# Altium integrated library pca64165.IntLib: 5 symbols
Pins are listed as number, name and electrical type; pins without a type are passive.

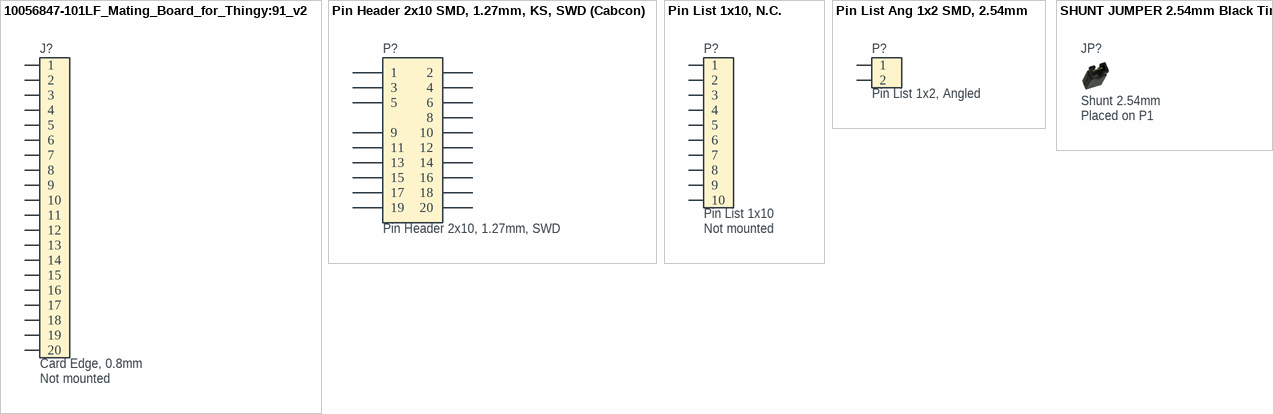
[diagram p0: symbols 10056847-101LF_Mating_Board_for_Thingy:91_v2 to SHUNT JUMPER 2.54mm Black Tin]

## 10056847-101LF_Mating_Board_for_Thingy:91_v2
designator J?, comment Card Edge, 0.8mm  Assembly: Not mounted  (no BOM)
0.8mm pitch, dual edge, right angle, SMD, card edge connector; Part Number: 10056847-101LF_Mating_Board_for_Thingy:91_v2; Manufacturer: FCI; Manufacturer Part Number: 10056847-101LF; Part number NEMS: 100500798; Component Status: Active; Pad Count: 20; Note: N.A.
footprint 10056847-101LF_Mating_Board_Thingy91_v2
pins: 1, 2, 3, 4, 5, 6, 7, 8, 9, 10, 11, 12, 13, 14, 15, 16, 17, 18, 19, 20
1 alternate drawing of the same symbol

## Pin Header 2x10 SMD, 1.27mm, KS, SWD (Cabcon)
designator P?, comment Pin Header 2x10, 1.27mm, SWD
Pin Header 2x10, 1.27mm (50mil), SMD, Keying Shroud, Removed Pin 7; Part Number: Pin Header 2x10 SMD, 1.27mm, KS, SWD (Cabcon); Manufacturer: WCON; Manufacturer Part Number: 3132-20MS0BK00R5; Part number NEMS: 100500841,100500280; Note: (Replaced 3132-20MS0BK00R3); Artikkelnr Noca: N.A.; Pad Count: 19; Component Status: Active; System: Connector
footprint HDR_2x10-SMD-1.27mm-K-SWD
pins: 1, 2, 3, 4, 5, 6, 8, 9, 10, 11, 12, 13, 14, 15, 16, 17, 18, 19, 20

## Pin List 1x10, N.C.
designator P?, comment Pin List 1x10  Assembly: Not mounted
Pin List 1x10, 2.54mm (100mil); Part Number: Pin List 1x10, N.C.; Manufacturer: N.A.; Part number NEMS: 100500336; Pad Count: 10; Component Status: Active; System: Connector
footprint LIST_1x10-NC
pins: 1, 2, 3, 4, 5, 6, 7, 8, 9, 10
1 alternate drawing of the same symbol

## Pin List Ang 1x2 SMD, 2.54mm
designator P?, comment Pin List 1x2, Angled
Pin List 1x2, 2.54mm (100mil), Right Angled, SMD; Part Number: Pin List Ang 1x2 SMD, 2.54mm; Manufacturer: WCON; Manufacturer Part Number: 1125B-1102S0Z135CR06; Part number NEMS: 100500354; Note: (Replaced 1125B-1102S0Z135R2); Artikkelnr Noca: N.A.; Pad Count: 2; Component Status: Active; System: Connector
footprint LIST_ANG_1x2-SMD-2.54MM
pins: 1, 2

## SHUNT JUMPER 2.54mm Black Tin
designator JP?, comment Shunt 2.54mm  Assembly: Placed on P1
Shunt Jumper 2.54mm Black, open top; Part Number: SHUNT JUMPER 2.54mm Black Tin; Manufacturer: WCON; Manufacturer Part Number: 3710-6001OS0B05; Part number NEMS: 100500728; Pad Count: 2; Note: N.A.; Component Status: Active; System: Connector
footprint Shunt_2.54mm_Horizontal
